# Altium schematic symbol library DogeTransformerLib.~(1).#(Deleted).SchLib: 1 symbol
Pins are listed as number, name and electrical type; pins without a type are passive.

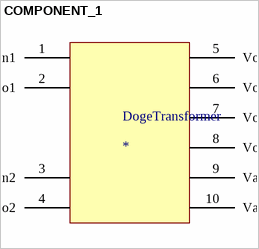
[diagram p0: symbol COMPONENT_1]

## COMPONENT_1
designator DogeTransformer
Doge
footprint transformer
pins: 1 Vin1, 2 Vino1, 3 Vin2, 4 Vino2, 5 Vout1, 6 Vouto1, 7 Vout2, 8 Vouto2, 9 Vaux, 10 Vauxo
